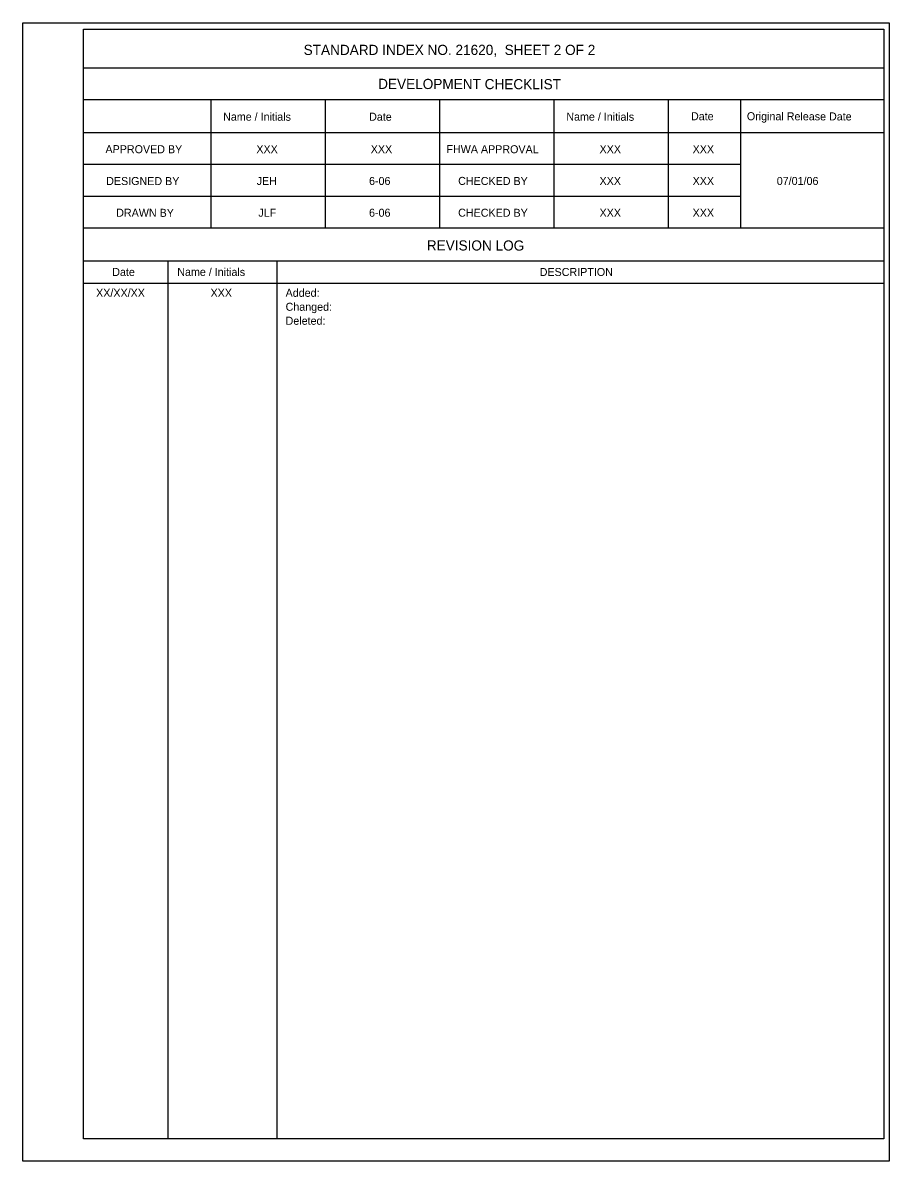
# Model space of a CAD drawing. Extents: x 10624 to 10731, y 76457 to 76509.
# Drawn here: x 10698.18 to 10730.9, y 76465.91 to 76508.91 of the extents above; entities that cross this region are included whole.
import ezdxf

# ---------------------------------------------------------------- set-up
doc = ezdxf.new("R2010")
doc.units = 0
for name, color, linetype in [('Border', 7, 'Continuous'), ('PlotBorder_dp', 7, 'Continuous'), ('TextStructures', 7, 'Continuous')]:
    doc.layers.add(name, color=color, linetype=linetype)

msp = doc.modelspace()

# ---------------------------------------------------------------- linework, layer by layer
at = {"layer": 'Border'}
for p, q in [((10730.698, 76507.194), (10700.478, 76507.194)), ((10730.698, 76505.994), (10700.478, 76505.994)), ((10705.278, 76505.994), (10705.278, 76501.153)), ((10709.598, 76505.994), (10709.598, 76501.153)), ((10713.918, 76505.994), (10713.918, 76501.153)), ((10718.238, 76505.994), (10718.238, 76501.153)), ((10722.558, 76505.994), (10722.558, 76501.153)), ((10725.28, 76505.994), (10725.28, 76501.153)), ((10730.698, 76504.753), (10700.478, 76504.753)), ((10725.28, 76503.553), (10700.478, 76503.553)), ((10725.28, 76502.353), (10700.478, 76502.353)), ((10730.698, 76501.153), (10700.478, 76501.153)), ((10730.698, 76499.911), (10700.478, 76499.911)), ((10703.658, 76499.911), (10703.658, 76466.751)), ((10707.772, 76499.911), (10707.772, 76466.751)), ((10730.698, 76499.065), (10700.478, 76499.065))]:
    msp.add_line(p, q, dxfattribs=at)
msp.add_lwpolyline([(10700.478, 76508.665), (10730.698, 76508.665), (10730.698, 76466.751), (10700.478, 76466.751)], close=True, dxfattribs=at)
at = {"layer": 'PlotBorder_dp'}
msp.add_line((10698.182, 76465.909), (10698.182, 76465.909), dxfattribs=at)
msp.add_lwpolyline([(10698.182, 76508.909), (10730.902, 76508.909), (10730.902, 76465.909), (10698.182, 76465.909)], close=True, dxfattribs=at)

# ---------------------------------------------------------------- texts
at = {"layer": 'TextStructures'}
for s, height, p in [('STANDARD INDEX NO. 21620,  SHEET 2 OF 2', 0.384, (10708.788, 76507.693)), ('XXX', 0.3024, (10707.003, 76503.983)), ('XXX', 0.3024, (10711.323, 76503.983)), ('XXX', 0.3024, (10719.963, 76503.983)), ('XXX', 0.3024, (10723.478, 76503.983)), ('JEH', 0.3024, (10707.014, 76502.783)), ('6-06', 0.3024, (10711.258, 76502.783)), ('XXX', 0.3024, (10719.963, 76502.783)), ('XXX', 0.3024, (10723.478, 76502.783)), ('07/01/06', 0.3024, (10726.655, 76502.783)), ('JLF', 0.3024, (10707.077, 76501.583)), ('6-06', 0.3024, (10711.258, 76501.583)), ('XXX', 0.3024, (10719.963, 76501.583)), ('XXX', 0.3024, (10723.478, 76501.583)), ('DESCRIPTION', 0.3024, (10717.703, 76499.345)), ('XX/XX/XX', 0.3024, (10700.951, 76498.558)), ('XXX', 0.3024, (10705.273, 76498.558)), ('Added:', 0.3024, (10708.107, 76498.558)), ('Changed:', 0.3024, (10708.107, 76498.031)), ('Deleted:', 0.3024, (10708.107, 76497.503))]:
    msp.add_text(s, height=height, dxfattribs=at).set_placement(p)
for s, height, p in [('DEVELOPMENT CHECKLIST', 0.384, (10711.601, 76506.41)), ('Name / Initials', 0.3024, (10705.747, 76505.213)), ('Date', 0.3024, (10711.259, 76505.21)), ('Name / Initials', 0.3024, (10718.707, 76505.213)), ('Date', 0.3024, (10723.416, 76505.228)), ('Original Release Date', 0.3024, (10725.526, 76505.228)), ('APPROVED BY', 0.3024, (10701.305, 76503.985)), ('FHWA APPROVAL', 0.3024, (10714.18, 76503.986)), ('DESIGNED BY', 0.3024, (10701.331, 76502.783)), ('CHECKED BY', 0.3024, (10714.623, 76502.785)), ('DRAWN BY', 0.3024, (10701.71, 76501.583)), ('CHECKED BY', 0.3024, (10714.623, 76501.585)), ('REVISION LOG', 0.384, (10713.439, 76500.311)), ('Date', 0.3024, (10701.561, 76499.346)), ('Name / Initials', 0.3024, (10704.016, 76499.349))]:
    msp.add_text(s, height=height, rotation=359.8756, dxfattribs=at).set_placement(p)

doc.saveas('drawing.dxf')
